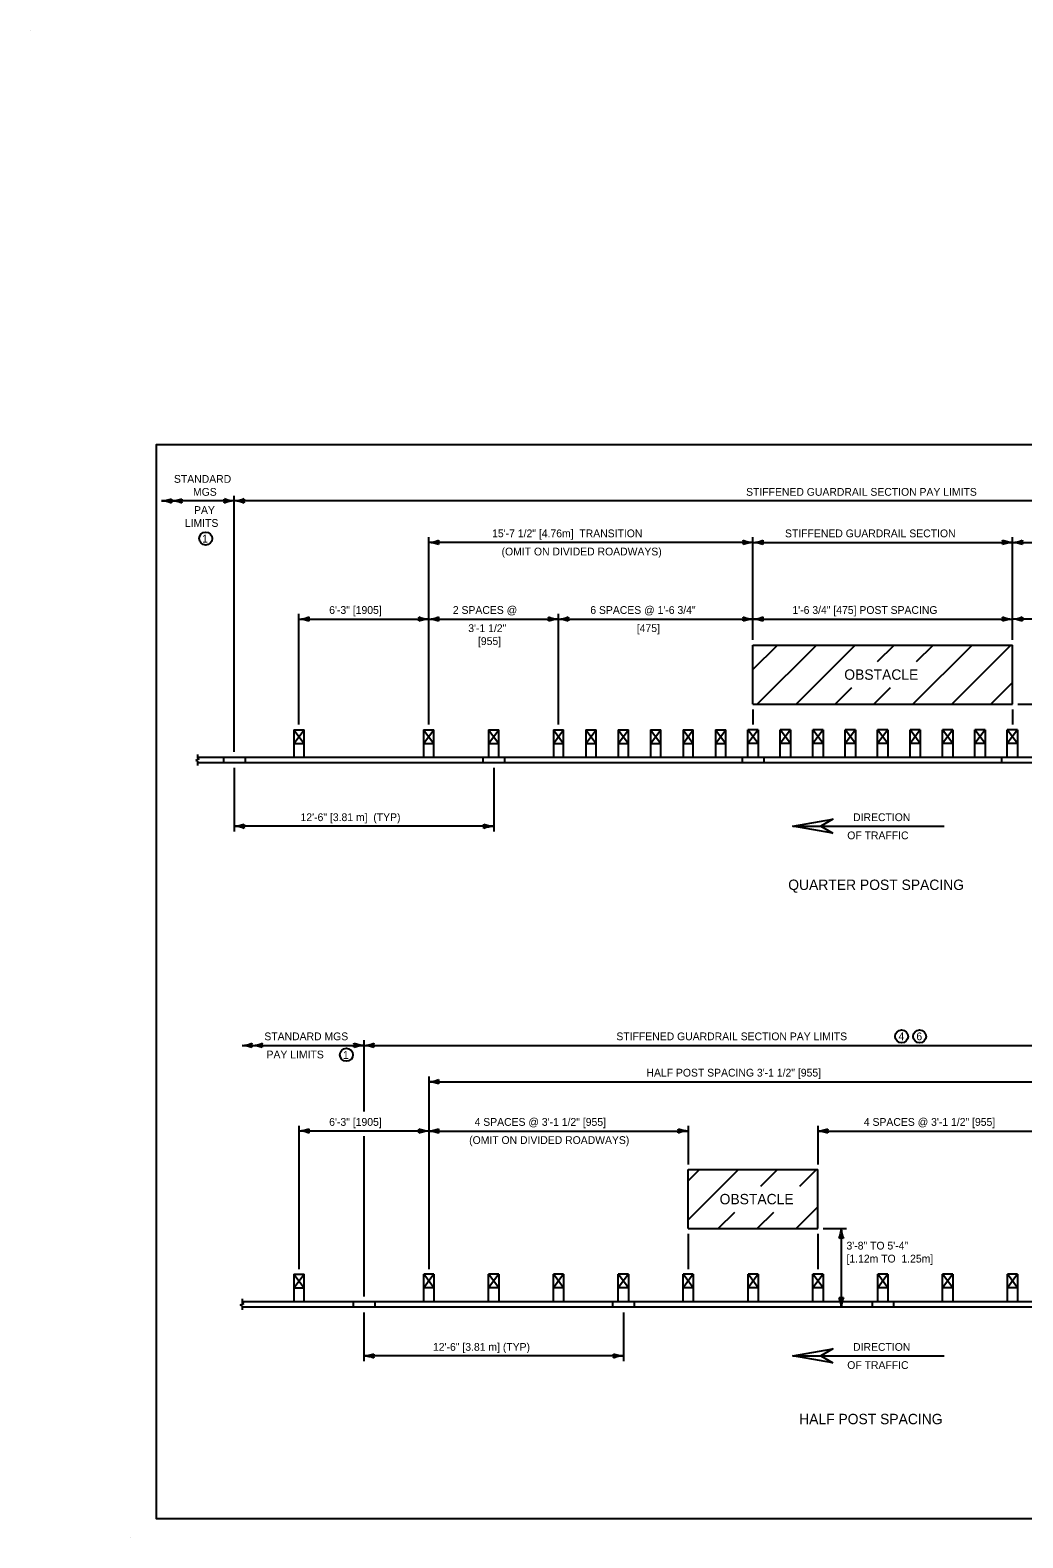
# Model space of a CAD drawing. Extents: x 49991.4 to 50044.5, y 49987.6 to 50011.4.
# Drawn here: x 50008.76 to 50016.42, y 49999.74 to 50011.36 of the extents above; entities that cross this region are included whole.
import ezdxf

# ---------------------------------------------------------------- set-up
doc = ezdxf.new("R2010")
doc.units = 0
for name, color, linetype in [('Level 1', 7, 'Continuous'), ('Level 2', 7, 'Continuous'), ('Level 3', 7, 'Continuous'), ('Level 4', 7, 'Continuous'), ('Level 6', 7, 'Continuous')]:
    doc.layers.add(name, color=color, linetype=linetype)

msp = doc.modelspace()

# ---------------------------------------------------------------- linework, layer by layer
at = {"layer": 'Level 1'}
for p, q in [((50008.765, 50011.363), (50008.765, 50011.363)), ((50014.337, 50006.621), (50016.338, 50006.621)), ((50014.337, 50006.165), (50014.337, 50006.621)), ((50014.337, 50006.433), (50014.526, 50006.621)), ((50014.37, 50006.165), (50014.826, 50006.621)), ((50014.67, 50006.165), (50015.126, 50006.621)), ((50015.298, 50006.493), (50015.426, 50006.621)), ((50015.57, 50006.165), (50016.026, 50006.621)), ((50015.598, 50006.493), (50015.726, 50006.621)), ((50015.87, 50006.165), (50016.325, 50006.621)), ((50016.338, 50006.165), (50016.338, 50006.621)), ((50014.97, 50006.165), (50015.098, 50006.293)), ((50015.27, 50006.165), (50015.398, 50006.293)), ((50016.17, 50006.165), (50016.338, 50006.333)), ((50014.337, 50006.165), (50016.338, 50006.165)), ((50010.798, 50005.967), (50010.798, 50005.757)), ((50010.798, 50005.862), (50010.877, 50005.967)), ((50010.798, 50005.967), (50010.877, 50005.862)), ((50010.798, 50005.967), (50010.877, 50005.967)), ((50010.877, 50005.757), (50010.877, 50005.967)), ((50011.798, 50005.967), (50011.798, 50005.757)), ((50011.798, 50005.862), (50011.877, 50005.967)), ((50011.798, 50005.967), (50011.877, 50005.862)), ((50011.798, 50005.967), (50011.877, 50005.967)), ((50011.877, 50005.757), (50011.877, 50005.967)), ((50012.298, 50005.967), (50012.298, 50005.757)), ((50012.298, 50005.862), (50012.377, 50005.967)), ((50012.298, 50005.967), (50012.377, 50005.862)), ((50012.298, 50005.967), (50012.377, 50005.967)), ((50012.377, 50005.757), (50012.377, 50005.967)), ((50012.798, 50005.967), (50012.798, 50005.757)), ((50012.798, 50005.862), (50012.877, 50005.967)), ((50012.798, 50005.967), (50012.877, 50005.862)), ((50012.798, 50005.967), (50012.877, 50005.967)), ((50012.877, 50005.757), (50012.877, 50005.967)), ((50013.048, 50005.967), (50013.048, 50005.757)), ((50013.048, 50005.862), (50013.127, 50005.967)), ((50013.048, 50005.967), (50013.127, 50005.862)), ((50013.048, 50005.967), (50013.127, 50005.967)), ((50013.127, 50005.757), (50013.127, 50005.967)), ((50013.298, 50005.967), (50013.298, 50005.757)), ((50013.298, 50005.862), (50013.377, 50005.967)), ((50013.298, 50005.967), (50013.377, 50005.862)), ((50013.298, 50005.967), (50013.377, 50005.967)), ((50013.377, 50005.757), (50013.377, 50005.967)), ((50013.548, 50005.967), (50013.548, 50005.757)), ((50013.548, 50005.862), (50013.627, 50005.967)), ((50013.548, 50005.967), (50013.627, 50005.862)), ((50013.548, 50005.967), (50013.627, 50005.967)), ((50013.627, 50005.757), (50013.627, 50005.967)), ((50013.798, 50005.967), (50013.798, 50005.757)), ((50013.798, 50005.862), (50013.877, 50005.967)), ((50013.798, 50005.967), (50013.877, 50005.862)), ((50013.798, 50005.967), (50013.877, 50005.967)), ((50013.877, 50005.757), (50013.877, 50005.967)), ((50014.048, 50005.967), (50014.048, 50005.757)), ((50014.048, 50005.862), (50014.127, 50005.967)), ((50014.048, 50005.967), (50014.127, 50005.862)), ((50014.048, 50005.967), (50014.127, 50005.967)), ((50014.127, 50005.757), (50014.127, 50005.967)), ((50014.298, 50005.757), (50014.298, 50005.967)), ((50014.377, 50005.862), (50014.298, 50005.967)), ((50014.377, 50005.967), (50014.298, 50005.862)), ((50014.377, 50005.967), (50014.298, 50005.967)), ((50014.377, 50005.967), (50014.377, 50005.757)), ((50014.548, 50005.757), (50014.548, 50005.967)), ((50014.627, 50005.862), (50014.548, 50005.967)), ((50014.627, 50005.967), (50014.548, 50005.862)), ((50014.627, 50005.967), (50014.548, 50005.967)), ((50014.627, 50005.967), (50014.627, 50005.757)), ((50014.798, 50005.757), (50014.798, 50005.967)), ((50014.877, 50005.862), (50014.798, 50005.967)), ((50014.877, 50005.967), (50014.798, 50005.862)), ((50014.877, 50005.967), (50014.798, 50005.967)), ((50014.877, 50005.967), (50014.877, 50005.757)), ((50015.048, 50005.757), (50015.048, 50005.967)), ((50015.127, 50005.862), (50015.048, 50005.967)), ((50015.127, 50005.967), (50015.048, 50005.862)), ((50015.127, 50005.967), (50015.048, 50005.967)), ((50015.127, 50005.967), (50015.127, 50005.757)), ((50015.298, 50005.757), (50015.298, 50005.967)), ((50015.377, 50005.862), (50015.298, 50005.967)), ((50015.377, 50005.967), (50015.298, 50005.862)), ((50015.377, 50005.967), (50015.298, 50005.967)), ((50015.377, 50005.967), (50015.377, 50005.757)), ((50015.548, 50005.757), (50015.548, 50005.967)), ((50015.627, 50005.862), (50015.548, 50005.967)), ((50015.627, 50005.967), (50015.548, 50005.862)), ((50015.627, 50005.967), (50015.548, 50005.967)), ((50015.627, 50005.967), (50015.627, 50005.757)), ((50015.798, 50005.757), (50015.798, 50005.967)), ((50015.877, 50005.862), (50015.798, 50005.967)), ((50015.877, 50005.967), (50015.798, 50005.862)), ((50015.877, 50005.967), (50015.798, 50005.967)), ((50015.877, 50005.967), (50015.877, 50005.757)), ((50016.048, 50005.757), (50016.048, 50005.967)), ((50016.127, 50005.862), (50016.048, 50005.967)), ((50016.127, 50005.967), (50016.048, 50005.862)), ((50016.127, 50005.967), (50016.048, 50005.967)), ((50016.127, 50005.967), (50016.127, 50005.757)), ((50016.298, 50005.757), (50016.298, 50005.967)), ((50016.377, 50005.862), (50016.298, 50005.967)), ((50016.377, 50005.967), (50016.298, 50005.862)), ((50016.377, 50005.967), (50016.298, 50005.967)), ((50016.377, 50005.967), (50016.377, 50005.757)), ((50010.798, 50005.862), (50010.877, 50005.862)), ((50011.798, 50005.862), (50011.877, 50005.862)), ((50012.298, 50005.862), (50012.377, 50005.862)), ((50012.798, 50005.862), (50012.877, 50005.862)), ((50013.048, 50005.862), (50013.127, 50005.862)), ((50013.298, 50005.862), (50013.377, 50005.862)), ((50013.548, 50005.862), (50013.627, 50005.862)), ((50013.798, 50005.862), (50013.877, 50005.862)), ((50014.048, 50005.862), (50014.127, 50005.862)), ((50014.377, 50005.862), (50014.298, 50005.862)), ((50014.627, 50005.862), (50014.548, 50005.862)), ((50014.877, 50005.862), (50014.798, 50005.862)), ((50015.127, 50005.862), (50015.048, 50005.862)), ((50015.377, 50005.862), (50015.298, 50005.862)), ((50015.627, 50005.862), (50015.548, 50005.862)), ((50015.877, 50005.862), (50015.798, 50005.862)), ((50016.127, 50005.862), (50016.048, 50005.862)), ((50016.377, 50005.862), (50016.298, 50005.862)), ((50010.054, 50005.757), (50020.621, 50005.757)), ((50020.621, 50005.713), (50010.054, 50005.713)), ((50010.254, 50005.757), (50010.254, 50005.713)), ((50012.254, 50005.757), (50012.254, 50005.713)), ((50014.254, 50005.757), (50014.254, 50005.713)), ((50014.254, 50005.757), (50014.254, 50005.713)), ((50016.254, 50005.757), (50016.254, 50005.713)), ((50014.645, 50005.223), (50015.811, 50005.223)), ((50013.838, 50002.576), (50014.838, 50002.576)), ((50013.838, 50002.188), (50014.226, 50002.576)), ((50013.838, 50002.488), (50013.926, 50002.576)), ((50013.838, 50002.12), (50013.838, 50002.576)), ((50014.398, 50002.448), (50014.526, 50002.576)), ((50014.698, 50002.448), (50014.826, 50002.576)), ((50014.838, 50002.12), (50014.838, 50002.576)), ((50014.07, 50002.12), (50014.198, 50002.248)), ((50014.37, 50002.12), (50014.498, 50002.248)), ((50014.67, 50002.12), (50014.838, 50002.288)), ((50013.838, 50002.12), (50014.838, 50002.12)), ((50010.798, 50001.768), (50010.798, 50001.558)), ((50010.798, 50001.663), (50010.877, 50001.768)), ((50010.798, 50001.768), (50010.877, 50001.663)), ((50010.798, 50001.768), (50010.877, 50001.768)), ((50010.877, 50001.558), (50010.877, 50001.768)), ((50011.799, 50001.558), (50011.799, 50001.768)), ((50011.877, 50001.663), (50011.799, 50001.768)), ((50011.877, 50001.768), (50011.799, 50001.663)), ((50011.877, 50001.768), (50011.799, 50001.768)), ((50011.877, 50001.768), (50011.877, 50001.558)), ((50012.299, 50001.558), (50012.299, 50001.768)), ((50012.377, 50001.663), (50012.299, 50001.768)), ((50012.377, 50001.768), (50012.299, 50001.663)), ((50012.377, 50001.768), (50012.299, 50001.768)), ((50012.377, 50001.768), (50012.377, 50001.558)), ((50012.799, 50001.558), (50012.799, 50001.768)), ((50012.877, 50001.663), (50012.799, 50001.768)), ((50012.877, 50001.768), (50012.799, 50001.663)), ((50012.877, 50001.768), (50012.799, 50001.768)), ((50012.877, 50001.768), (50012.877, 50001.558)), ((50013.299, 50001.558), (50013.299, 50001.768)), ((50013.377, 50001.663), (50013.299, 50001.768)), ((50013.377, 50001.768), (50013.299, 50001.663)), ((50013.377, 50001.768), (50013.299, 50001.768)), ((50013.377, 50001.768), (50013.377, 50001.558)), ((50013.799, 50001.558), (50013.799, 50001.768)), ((50013.877, 50001.663), (50013.799, 50001.768)), ((50013.877, 50001.768), (50013.799, 50001.663)), ((50013.877, 50001.768), (50013.799, 50001.768)), ((50013.877, 50001.768), (50013.877, 50001.558)), ((50014.299, 50001.558), (50014.299, 50001.768)), ((50014.377, 50001.663), (50014.299, 50001.768)), ((50014.377, 50001.768), (50014.299, 50001.663)), ((50014.377, 50001.768), (50014.299, 50001.768)), ((50014.377, 50001.768), (50014.377, 50001.558)), ((50014.799, 50001.558), (50014.799, 50001.768)), ((50014.877, 50001.663), (50014.799, 50001.768)), ((50014.877, 50001.768), (50014.799, 50001.663)), ((50014.877, 50001.768), (50014.799, 50001.768)), ((50014.877, 50001.768), (50014.877, 50001.558)), ((50015.299, 50001.558), (50015.299, 50001.768)), ((50015.377, 50001.663), (50015.299, 50001.768)), ((50015.377, 50001.768), (50015.299, 50001.663)), ((50015.377, 50001.768), (50015.299, 50001.768)), ((50015.377, 50001.768), (50015.377, 50001.558)), ((50015.799, 50001.558), (50015.799, 50001.768)), ((50015.877, 50001.663), (50015.799, 50001.768)), ((50015.877, 50001.768), (50015.799, 50001.663)), ((50015.877, 50001.768), (50015.799, 50001.768)), ((50015.877, 50001.768), (50015.877, 50001.558)), ((50016.299, 50001.558), (50016.299, 50001.768)), ((50016.377, 50001.663), (50016.299, 50001.768)), ((50016.377, 50001.768), (50016.299, 50001.663)), ((50016.377, 50001.768), (50016.299, 50001.768)), ((50016.377, 50001.768), (50016.377, 50001.558)), ((50010.798, 50001.663), (50010.877, 50001.663)), ((50011.877, 50001.663), (50011.799, 50001.663)), ((50012.377, 50001.663), (50012.299, 50001.663)), ((50012.877, 50001.663), (50012.799, 50001.663)), ((50013.377, 50001.663), (50013.299, 50001.663)), ((50013.877, 50001.663), (50013.799, 50001.663)), ((50014.377, 50001.663), (50014.299, 50001.663)), ((50014.877, 50001.663), (50014.799, 50001.663)), ((50015.377, 50001.663), (50015.299, 50001.663)), ((50015.877, 50001.663), (50015.799, 50001.663)), ((50016.377, 50001.663), (50016.299, 50001.663)), ((50010.398, 50001.558), (50018.277, 50001.558)), ((50018.277, 50001.514), (50010.398, 50001.514)), ((50011.254, 50001.558), (50011.254, 50001.514)), ((50013.255, 50001.558), (50013.255, 50001.514)), ((50015.255, 50001.558), (50015.255, 50001.514)), ((50014.645, 50001.138), (50015.811, 50001.138)), ((50009.537, 49999.736), (50009.537, 49999.736))]:
    msp.add_line(p, q, dxfattribs=at)
for points in [[(50020.938, 50008.165), (50009.737, 50008.165), (50009.737, 49999.886), (50020.938, 49999.886)], [(50014.953, 50005.169), (50014.645, 50005.223), (50014.953, 50005.278), (50014.859, 50005.223)], [(50014.953, 50001.084), (50014.645, 50001.138), (50014.953, 50001.193), (50014.859, 50001.138)]]:
    msp.add_lwpolyline(points, close=True, dxfattribs=at)
at = {"layer": 'Level 2'}
for centre in [(50010.118, 50007.442), (50015.483, 50003.603), (50015.622, 50003.603), (50011.203, 50003.461)]:
    msp.add_circle(centre, 0.05, dxfattribs=at)
at = {"layer": 'Level 3'}
for p, q in [((50020.898, 50007.732), (50009.777, 50007.732)), ((50010.338, 50005.797), (50010.338, 50007.772)), ((50011.838, 50006.007), (50011.838, 50007.452)), ((50014.337, 50006.661), (50014.337, 50007.452)), ((50016.338, 50006.661), (50016.338, 50007.452)), ((50014.337, 50007.412), (50011.838, 50007.412)), ((50014.338, 50007.412), (50016.338, 50007.412)), ((50016.338, 50007.412), (50018.838, 50007.412)), ((50010.837, 50006.007), (50010.837, 50006.861)), ((50012.838, 50006.007), (50012.838, 50006.861)), ((50010.837, 50006.821), (50011.838, 50006.821)), ((50011.838, 50006.821), (50012.838, 50006.821)), ((50012.838, 50006.821), (50014.337, 50006.821)), ((50014.337, 50006.821), (50016.338, 50006.821)), ((50017.838, 50006.821), (50016.338, 50006.821)), ((50016.378, 50006.165), (50016.503, 50006.165)), ((50014.337, 50006.125), (50014.337, 50006.007)), ((50016.338, 50006.125), (50016.338, 50006.007)), ((50010.338, 50005.673), (50010.338, 50005.183)), ((50012.338, 50005.673), (50012.338, 50005.183)), ((50012.338, 50005.223), (50010.338, 50005.223)), ((50010.398, 50003.533), (50018.277, 50003.533)), ((50011.338, 50003.573), (50011.338, 50003.023)), ((50011.838, 50003.293), (50011.838, 50001.808)), ((50011.838, 50003.253), (50016.838, 50003.253)), ((50010.837, 50002.913), (50010.837, 50001.808)), ((50013.838, 50002.913), (50013.838, 50002.616)), ((50014.838, 50002.913), (50014.838, 50002.616)), ((50011.838, 50002.873), (50010.837, 50002.873)), ((50011.338, 50002.833), (50011.338, 50001.598)), ((50011.838, 50002.873), (50013.838, 50002.873)), ((50014.838, 50002.873), (50016.838, 50002.873)), ((50013.838, 50002.08), (50013.838, 50001.808)), ((50014.838, 50002.08), (50014.838, 50001.808)), ((50014.878, 50002.12), (50015.058, 50002.12)), ((50015.018, 50002.12), (50015.018, 50001.514)), ((50011.338, 50001.474), (50011.338, 50001.098)), ((50013.338, 50001.474), (50013.338, 50001.098)), ((50013.338, 50001.138), (50011.338, 50001.138))]:
    msp.add_line(p, q, dxfattribs=at)
for centre, radius, start, end in [((50009.766, 50007.965), 0.233, 272.8273, 292.0772), ((50009.768, 50007.51), 0.222, 67.456, 87.6395), ((50009.906, 50007.732), 0.0548, 162.1388, 197.8612), ((50009.846, 50007.965), 0.233, 272.8273, 292.0772), ((50009.848, 50007.51), 0.222, 67.456, 87.6395), ((50009.986, 50007.732), 0.0548, 162.1388, 197.8612), ((50010.347, 50007.955), 0.222, 247.456, 267.6395), ((50010.209, 50007.732), 0.0548, 342.1388, 17.8612), ((50010.349, 50007.5), 0.233, 92.8273, 112.0772), ((50010.329, 50007.955), 0.222, 272.3605, 292.544), ((50010.326, 50007.5), 0.233, 67.9228, 87.1727), ((50010.466, 50007.732), 0.0548, 162.1388, 197.8612), ((50011.826, 50007.645), 0.233, 272.8273, 292.0772), ((50011.966, 50007.412), 0.0548, 162.1388, 197.8612), ((50014.209, 50007.412), 0.0548, 342.1388, 17.8612), ((50014.349, 50007.645), 0.233, 247.9228, 267.1727), ((50014.326, 50007.645), 0.233, 272.8273, 292.0772), ((50014.466, 50007.412), 0.0548, 162.1388, 197.8612), ((50016.347, 50007.635), 0.222, 247.456, 267.6395), ((50016.209, 50007.412), 0.0548, 342.1388, 17.8612), ((50016.326, 50007.645), 0.233, 272.8273, 292.0772), ((50016.466, 50007.412), 0.0548, 162.1388, 197.8612), ((50011.828, 50007.19), 0.222, 67.456, 87.6395), ((50014.347, 50007.19), 0.222, 92.3605, 112.544), ((50014.328, 50007.19), 0.222, 67.456, 87.6395), ((50016.349, 50007.18), 0.233, 92.8273, 112.0772), ((50016.329, 50007.19), 0.222, 67.456, 87.6395), ((50010.828, 50007.043), 0.222, 272.3605, 292.544), ((50010.826, 50006.588), 0.233, 67.9228, 87.1727), ((50010.966, 50006.821), 0.0548, 162.1388, 197.8612), ((50011.709, 50006.821), 0.0548, 342.1388, 17.8612), ((50011.849, 50007.054), 0.233, 247.9228, 267.1727), ((50011.847, 50006.599), 0.222, 92.3605, 112.544), ((50011.828, 50007.043), 0.222, 272.3605, 292.544), ((50011.826, 50006.588), 0.233, 67.9228, 87.1727), ((50011.966, 50006.821), 0.0548, 162.1388, 197.8612), ((50012.709, 50006.821), 0.0548, 342.1388, 17.8612), ((50012.849, 50007.054), 0.233, 247.9228, 267.1727), ((50012.847, 50006.599), 0.222, 92.3605, 112.544), ((50012.828, 50007.043), 0.222, 272.3605, 292.544), ((50012.826, 50006.588), 0.233, 67.9228, 87.1727), ((50012.966, 50006.821), 0.0548, 162.1388, 197.8612), ((50014.209, 50006.821), 0.0548, 342.1388, 17.8612), ((50014.349, 50007.054), 0.233, 247.9228, 267.1727), ((50014.347, 50006.599), 0.222, 92.3605, 112.544), ((50014.328, 50006.599), 0.222, 67.456, 87.6395), ((50014.326, 50007.054), 0.233, 272.8273, 292.0772), ((50014.466, 50006.821), 0.0548, 162.1388, 197.8612), ((50016.347, 50007.043), 0.222, 247.456, 267.6395), ((50016.209, 50006.821), 0.0548, 342.1388, 17.8612), ((50016.349, 50006.588), 0.233, 92.8273, 112.0772), ((50016.326, 50007.054), 0.233, 272.8273, 292.0772), ((50016.329, 50006.599), 0.222, 67.456, 87.6395), ((50016.466, 50006.821), 0.0548, 162.1388, 197.8612), ((50010.326, 50005.456), 0.233, 272.8273, 292.0772), ((50010.329, 50005.001), 0.222, 67.456, 87.6395), ((50010.466, 50005.223), 0.0548, 162.1388, 197.8612), ((50012.347, 50005.445), 0.222, 247.456, 267.6395), ((50012.209, 50005.223), 0.0548, 342.1388, 17.8612), ((50012.349, 50004.99), 0.233, 92.8273, 112.0772), ((50010.387, 50003.766), 0.233, 272.8273, 292.0772), ((50010.389, 50003.311), 0.222, 67.456, 87.6395), ((50010.526, 50003.533), 0.0548, 162.1388, 197.8612), ((50010.467, 50003.766), 0.233, 272.8273, 292.0772), ((50010.469, 50003.311), 0.222, 67.456, 87.6395), ((50010.606, 50003.533), 0.0548, 162.1388, 197.8612), ((50011.347, 50003.756), 0.222, 247.456, 267.6395), ((50011.209, 50003.533), 0.0548, 342.1388, 17.8612), ((50011.349, 50003.301), 0.233, 92.8273, 112.0772), ((50011.326, 50003.766), 0.233, 272.8273, 292.0772), ((50011.329, 50003.311), 0.222, 67.456, 87.6395), ((50011.466, 50003.533), 0.0548, 162.1388, 197.8612), ((50011.826, 50003.486), 0.233, 272.8273, 292.0772), ((50011.829, 50003.031), 0.222, 67.456, 87.6395), ((50011.966, 50003.253), 0.0548, 162.1388, 197.8612), ((50010.828, 50003.096), 0.222, 272.3605, 292.544), ((50010.966, 50002.873), 0.0548, 162.1388, 197.8612), ((50011.709, 50002.873), 0.0548, 342.1388, 17.8612), ((50011.849, 50003.106), 0.233, 247.9228, 267.1727), ((50011.826, 50003.106), 0.233, 272.8273, 292.0772), ((50011.966, 50002.873), 0.0548, 162.1388, 197.8612), ((50013.847, 50003.096), 0.222, 247.456, 267.6395), ((50013.709, 50002.873), 0.0548, 342.1388, 17.8612), ((50014.826, 50003.106), 0.233, 272.8273, 292.0772), ((50014.966, 50002.873), 0.0548, 162.1388, 197.8612), ((50010.826, 50002.641), 0.233, 67.9228, 87.1727), ((50011.847, 50002.651), 0.222, 92.3605, 112.544), ((50011.829, 50002.651), 0.222, 67.456, 87.6395), ((50013.849, 50002.641), 0.233, 92.8273, 112.0772), ((50014.829, 50002.651), 0.222, 67.456, 87.6395), ((50014.785, 50002.132), 0.233, 337.9228, 357.1727), ((50015.24, 50002.129), 0.222, 182.3605, 202.544), ((50015.018, 50001.992), 0.0548, 72.1388, 107.8612), ((50014.796, 50001.505), 0.222, 2.3605, 22.544), ((50015.018, 50001.642), 0.0548, 252.1388, 287.8612), ((50015.251, 50001.502), 0.233, 157.9228, 177.1727), ((50011.326, 50001.371), 0.233, 272.8273, 292.0772), ((50011.466, 50001.138), 0.0548, 162.1388, 197.8612), ((50013.347, 50001.36), 0.222, 247.456, 267.6395), ((50013.209, 50001.138), 0.0548, 342.1388, 17.8612), ((50011.329, 50000.916), 0.222, 67.456, 87.6395), ((50013.349, 50000.906), 0.233, 92.8273, 112.0772)]:
    msp.add_arc(centre, radius, start, end, dxfattribs=at)
at = {"layer": 'Level 4'}
for p, q in [((50010.421, 50005.757), (50010.421, 50005.713)), ((50012.421, 50005.757), (50012.421, 50005.713)), ((50014.421, 50005.757), (50014.421, 50005.713)), ((50011.421, 50001.558), (50011.421, 50001.514)), ((50013.421, 50001.558), (50013.421, 50001.514)), ((50015.421, 50001.558), (50015.421, 50001.514))]:
    msp.add_line(p, q, dxfattribs=at)
at = {"layer": 'Level 6'}
for p, q in [((50010.068, 50005.74), (50010.041, 50005.73)), ((50010.054, 50005.725), (50010.041, 50005.73)), ((50010.054, 50005.777), (50010.054, 50005.745)), ((50010.068, 50005.74), (50010.054, 50005.745)), ((50010.054, 50005.725), (50010.054, 50005.693)), ((50010.412, 50001.541), (50010.384, 50001.531)), ((50010.398, 50001.526), (50010.384, 50001.531)), ((50010.398, 50001.578), (50010.398, 50001.546)), ((50010.412, 50001.541), (50010.398, 50001.546)), ((50010.398, 50001.526), (50010.398, 50001.494))]:
    msp.add_line(p, q, dxfattribs=at)

# ---------------------------------------------------------------- texts
at = {"layer": 'Level 2'}
for s, height, p in [('STANDARD', 0.06, (50009.873, 50007.872)), ('MGS', 0.06, (50010.02, 50007.772)), ('STIFFENED GUARDRAIL SECTION PAY LIMITS', 0.06, (50014.284, 50007.772)), ('PAY', 0.06, (50010.028, 50007.632)), ('LIMITS', 0.06, (50009.957, 50007.532)), ('1', 0.06, (50010.09, 50007.411)), ('15\'-7 1/2" [4.76m]  TRANSITION', 0.06, (50012.326, 50007.452)), ('STIFFENED GUARDRAIL SECTION', 0.06, (50014.584, 50007.452)), ('(OMIT ON DIVIDED ROADWAYS)', 0.06, (50012.399, 50007.312)), ('6\'-3" [1905]', 0.06, (50011.07, 50006.861)), (' 2 SPACES @ ', 0.06, (50012.001, 50006.861)), ('6 SPACES @ 1\'-6 3/4"', 0.06, (50013.083, 50006.861)), ('1\'-6 3/4" [475] POST SPACING', 0.06, (50014.641, 50006.861)), ('3\'-1 1/2"', 0.06, (50012.142, 50006.721)), (' [475]', 0.06, (50013.419, 50006.721)), ('[955]', 0.06, (50012.217, 50006.621)), ('OBSTACLE', 0.08, (50015.041, 50006.353)), ('12\'-6" [3.81 m]  (TYP)', 0.06, (50010.849, 50005.263)), ('DIRECTION', 0.06, (50015.109, 50005.263)), ('OF TRAFFIC', 0.06, (50015.064, 50005.123)), ('QUARTER POST SPACING', 0.08, (50014.609, 50004.732)), ('STANDARD MGS', 0.06, (50010.57, 50003.573)), ('STIFFENED GUARDRAIL SECTION PAY LIMITS', 0.06, (50013.284, 50003.573)), ('4', 0.06, (50015.459, 50003.573)), ('6', 0.06, (50015.597, 50003.573)), ('PAY LIMITS', 0.06, (50010.587, 50003.433)), ('1', 0.06, (50011.176, 50003.429)), ('HALF POST SPACING 3\'-1 1/2" [955]', 0.06, (50013.516, 50003.293)), ('6\'-3" [1905]', 0.06, (50011.07, 50002.913)), ('4 SPACES @ 3\'-1 1/2" [955]', 0.06, (50012.191, 50002.913)), ('4 SPACES @ 3\'-1 1/2" [955]', 0.06, (50015.192, 50002.913)), ('(OMIT ON DIVIDED ROADWAYS)', 0.06, (50012.149, 50002.773)), ('OBSTACLE', 0.08, (50014.08, 50002.308)), ('3\'-8" TO 5\'-4"', 0.06, (50015.058, 50001.959)), ('[1.12m TO  1.25m]', 0.06, (50015.058, 50001.859)), ('12\'-6" [3.81 m] (TYP)', 0.06, (50011.87, 50001.178)), ('DIRECTION', 0.06, (50015.109, 50001.178)), ('OF TRAFFIC', 0.06, (50015.064, 50001.038)), ('HALF POST SPACING', 0.08, (50014.693, 50000.612))]:
    msp.add_text(s, height=height, dxfattribs=at).set_placement(p)

doc.saveas('drawing.dxf')
